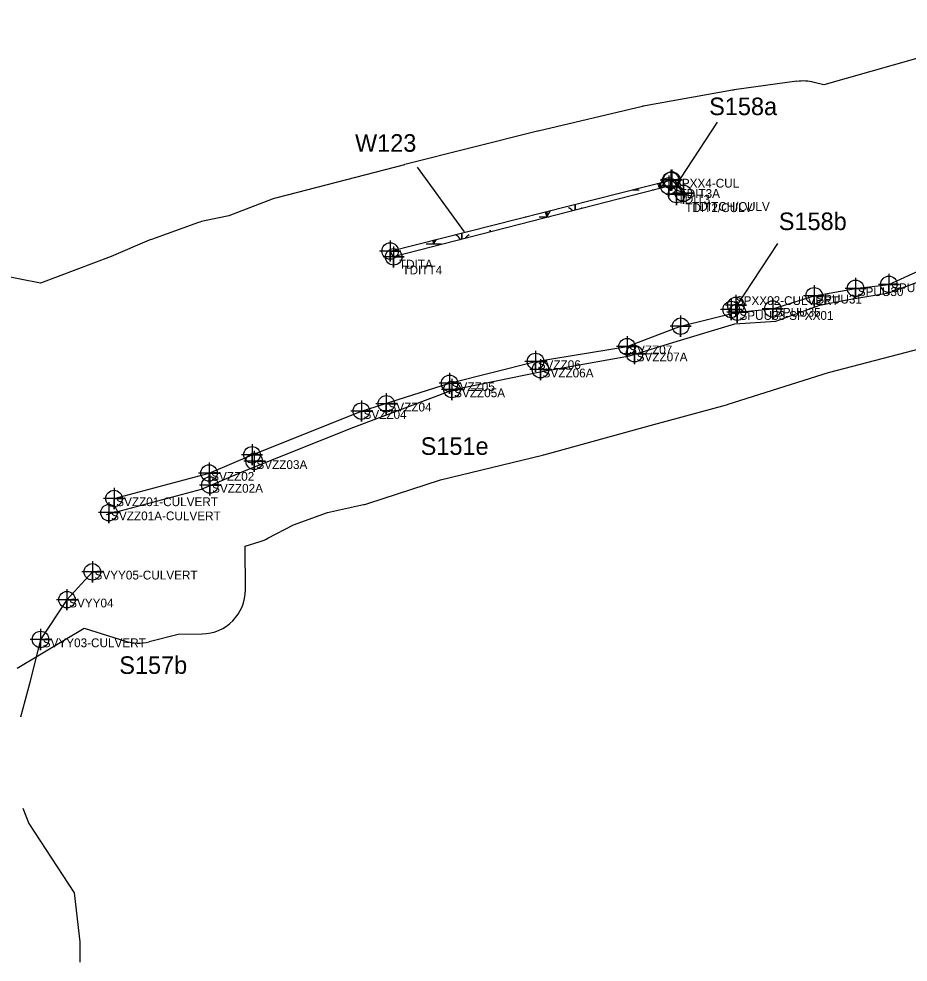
# Model space of a CAD drawing. Extents: x 1253697 to 1278588, y 912189 to 981699.
# Drawn here: x 1273061 to 1274074, y 979888 to 980962 of the extents above; entities that cross this region are included whole.
import ezdxf

# ---------------------------------------------------------------- set-up
doc = ezdxf.new("R2010")
doc.units = 0
for name, color, linetype in [('Default', 7, 'Continuous'), ('Exist Environmental Wetland Boundary', 7, 'Continuous'), ('Exist Environmental Wetland Boundary Cogo Comment', 7, 'Continuous'), ('Exist Environmental Wetland Boundary Cogo Number', 7, 'Continuous'), ('Exist Environmental Wetland Boundary Cogo Point CELL', 7, 'Continuous'), ('Exist Hydro Jurisdictional Stream or Body of Water Mitigable', 7, 'Continuous'), ('Exist Hydro Jurisdictional Stream or Body of Water Mitigable Cogo Comment', 7, 'Continuous'), ('Exist Hydro Jurisdictional Stream or Body of Water Mitigable Cogo Number', 7, 'Continuous'), ('Exist Hydro Jurisdictional Stream or Body of Water Mitigable Cogo Point CELL', 7, 'Continuous'), ('Exist Hydro Swamp or Marsh', 7, 'Continuous')]:
    doc.layers.add(name, color=color, linetype=linetype)

msp = doc.modelspace()

# ---------------------------------------------------------------- linework, layer by layer
at = {"layer": 'Default'}
for p, q in [((1273947.3, 980891.2), (1273875.7, 980881.4)), ((1273947.3, 980891.2), (1273875.7, 980881.4)), ((1273873.7, 980881), (1273774.2, 980863.3)), ((1273873.7, 980881), (1273774.2, 980863.3)), ((1273771.5, 980862.7), (1273652.5, 980834.5)), ((1273771.5, 980862.7), (1273652.5, 980834.5)), ((1273807.7, 980769.9), (1273856.7, 980844.7)), ((1273651.8, 980834.4), (1273500.5, 980796.4)), ((1273651.8, 980834.4), (1273500.5, 980796.4)), ((1273500.1, 980796.3), (1273354.7, 980758.6)), ((1273500.1, 980796.3), (1273354.7, 980758.6)), ((1273568.6, 980719.7), (1273514.9, 980793.6)), ((1273265.6, 980730.5), (1273212.1, 980711.2)), ((1273265.6, 980730.5), (1273212.1, 980711.2)), ((1273878.2, 980634.4), (1273925.6, 980706.7))]:
    msp.add_line(p, q, dxfattribs=at)
for points in [[(1274242.8, 980962.3), (1273978, 980887.1), (1273966.8, 980890)], [(1274242.8, 980962.3), (1273978, 980887.1), (1273966.8, 980890)], [(1273349.4, 980756.9), (1273300.1, 980738), (1273272.5, 980732.4)], [(1273349.4, 980756.9), (1273300.1, 980738), (1273272.5, 980732.4)], [(1273209.4, 980710.2), (1273166, 980691.7), (1273085.5, 980661.3), (1272899.9, 980697.9)], [(1273209.4, 980710.2), (1273166, 980691.7), (1273085.5, 980661.3), (1272899.9, 980697.9)], [(1273869, 980523.5), (1273983.3, 980559.8), (1274541, 980705)], [(1273869, 980523.5), (1273983.3, 980559.8), (1274541, 980705)], [(1273659.1, 980466), (1273784.3, 980500.3), (1273867.1, 980522.9)], [(1273659.1, 980466), (1273784.3, 980500.3), (1273867.1, 980522.9)], [(1273458.5, 980410.6), (1273541.2, 980437.5), (1273657.6, 980465.6)], [(1273458.5, 980410.6), (1273541.2, 980437.5), (1273657.6, 980465.6)], [(1273344.6, 980370.9), (1273373.8, 980386.3), (1273412.5, 980400.3), (1273453.7, 980409.3)], [(1273344.6, 980370.9), (1273373.8, 980386.3), (1273412.5, 980400.3), (1273453.7, 980409.3)], [(1273319, 980312.4), (1273318.6, 980362), (1273335.9, 980367.3)], [(1273319, 980312.4), (1273318.6, 980362), (1273335.9, 980367.3)], [(1273059, 980223.1), (1273135.4, 980268.4), (1273182.3, 980253.9)], [(1273059, 980223.1), (1273135.4, 980268.4), (1273182.3, 980253.9)], [(1273209.5, 980253.2), (1273242.4, 980261.7), (1273269.7, 980262)], [(1273209.5, 980253.2), (1273242.4, 980261.7), (1273269.7, 980262)]]:
    msp.add_lwpolyline(points, dxfattribs=at)
for centre, start, end in [((1273954.1, 980841.6), 75.3429, 97.8004), ((1273954.1, 980841.6), 75.3429, 97.8004), ((1273882.5, 980831.8), 97.8004, 100.1149), ((1273882.5, 980831.8), 97.8004, 100.1149), ((1273783, 980814.1), 100.1149, 103.3262), ((1273783, 980814.1), 100.1149, 103.3262), ((1273664, 980785.9), 103.3262, 104.0919), ((1273664, 980785.9), 103.3262, 104.0919), ((1273512.6, 980747.9), 104.0919, 104.5334), ((1273512.6, 980747.9), 104.0919, 104.5334), ((1273367.2, 980710.2), 104.5334, 110.925), ((1273367.2, 980710.2), 104.5334, 110.925), ((1273282.5, 980683.4), 101.5049, 109.7893), ((1273282.5, 980683.4), 101.5049, 109.7893), ((1273229, 980664.2), 109.7893, 113.0429), ((1273229, 980664.2), 109.7893, 113.0429), ((1273853.9, 980571.1), 285.2917, 287.6221), ((1273853.9, 980571.1), 285.2917, 287.6221), ((1273645.9, 980514.2), 283.5797, 285.3202), ((1273645.9, 980514.2), 283.5797, 285.3202), ((1273443, 980458.1), 282.3143, 288.0022), ((1273443, 980458.1), 282.3143, 288.0022), ((1273321.3, 980415.1), 287.0114, 297.8826), ((1273321.3, 980415.1), 287.0114, 297.8826), ((1273269, 980312), 270.8306, 0.3852), ((1273269, 980312), 270.8306, 0.3852), ((1273197.1, 980301.6), 252.8278, 284.412), ((1273197.1, 980301.6), 252.8278, 284.412)]:
    msp.add_arc(centre, 50, start, end, dxfattribs=at)
at = {"layer": 'Exist Environmental Wetland Boundary'}
msp.add_lwpolyline([(1273817.9, 980763.7), (1273801.3, 980772), (1273487.9, 980691.3), (1273483.9, 980698), (1273804.7, 980778.9)], close=True, dxfattribs=at)
at = {"layer": 'Exist Environmental Wetland Boundary Cogo Point CELL'}
for points in [[(1273803.5, 980790.5), (1273803.5, 980766.5), (1273803.5, 980778.5), (1273815.5, 980778.5), (1273791.5, 980778.5)], [(1273801.3, 980784), (1273801.3, 980760), (1273801.3, 980772), (1273813.3, 980772), (1273789.3, 980772)], [(1273817.9, 980775.7), (1273817.9, 980751.7), (1273817.9, 980763.7), (1273829.9, 980763.7), (1273805.9, 980763.7)], [(1273810.1, 980774.3), (1273810.1, 980750.3), (1273810.1, 980762.3), (1273822.1, 980762.3), (1273798.1, 980762.3)], [(1273483.9, 980710), (1273483.9, 980686), (1273483.9, 980698), (1273495.9, 980698), (1273471.9, 980698)], [(1273487.9, 980703.3), (1273487.9, 980679.3), (1273487.9, 980691.3), (1273499.9, 980691.3), (1273475.9, 980691.3)]]:
    msp.add_lwpolyline(points, dxfattribs=at)
for centre in [(1273803.5, 980778.5), (1273801.3, 980772), (1273810.1, 980762.3), (1273817.9, 980763.7), (1273483.9, 980698), (1273487.9, 980691.3)]:
    msp.add_circle(centre, 9.38, dxfattribs=at)
at = {"layer": 'Exist Hydro Jurisdictional Stream or Body of Water Mitigable'}
msp.add_line((1273804.7, 980778.9), (1273817.9, 980763.7), dxfattribs=at)
for points in [[(1273169.4, 980416.2), (1273277.6, 980445.2), (1273326.6, 980466), (1273451.1, 980515.7), (1273551.6, 980547.4), (1273649.5, 980572.3), (1273753.7, 980589.1), (1273814.8, 980612.4), (1273879.3, 980628.4), (1273919.7, 980632), (1273966.8, 980647), (1274014, 980655.5), (1274052, 980660), (1274091.9, 980678)], [(1273160.9, 980397.8), (1273269.1, 980426.8), (1273318.2, 980447.6), (1273442.6, 980497.3), (1273556.6, 980540.3), (1273654.8, 980560.5), (1273756.5, 980578.6), (1273810.9, 980595.4), (1273876.5, 980615.1), (1273923.2, 980618), (1273973.3, 980636.4), (1274004, 980642.3), (1274051.9, 980650.5), (1274089.4, 980664.5)], [(1273879.3, 980629.4), (1273877.7, 980636.2)], [(1273144.7, 980332.7), (1273115.8, 980301), (1273085.7, 980255.7), (1273073.6, 980206.8), (1273063, 980167.3)], [(1273065.4, 980063.7), (1273072.5, 980046), (1273123.9, 979967.1), (1273130.5, 979911.3), (1273130.4, 979888.3)]]:
    msp.add_lwpolyline(points, dxfattribs=at)
at = {"layer": 'Exist Hydro Jurisdictional Stream or Body of Water Mitigable Cogo Point CELL'}
for points in [[(1273804.7, 980790.9), (1273804.7, 980766.9), (1273804.7, 980778.9), (1273816.7, 980778.9), (1273792.7, 980778.9)], [(1274052, 980672), (1274052, 980648), (1274052, 980660), (1274064, 980660), (1274040, 980660)], [(1273966.8, 980659), (1273966.8, 980635), (1273966.8, 980647), (1273978.8, 980647), (1273954.8, 980647)], [(1274014, 980667.5), (1274014, 980643.5), (1274014, 980655.5), (1274026, 980655.5), (1274002, 980655.5)], [(1273877.7, 980648.2), (1273877.7, 980624.2), (1273877.7, 980636.2), (1273889.7, 980636.2), (1273865.7, 980636.2)], [(1273872.3, 980643.4), (1273872.3, 980619.4), (1273872.3, 980631.4), (1273884.3, 980631.4), (1273860.3, 980631.4)], [(1273879.3, 980640.4), (1273879.3, 980616.4), (1273879.3, 980628.4), (1273891.3, 980628.4), (1273867.3, 980628.4)], [(1273919.7, 980644), (1273919.7, 980620), (1273919.7, 980632), (1273931.7, 980632), (1273907.7, 980632)], [(1273814.8, 980624.4), (1273814.8, 980600.4), (1273814.8, 980612.4), (1273826.8, 980612.4), (1273802.8, 980612.4)], [(1273753.7, 980601.1), (1273753.7, 980577.1), (1273753.7, 980589.1), (1273765.7, 980589.1), (1273741.7, 980589.1)], [(1273762.2, 980593.1), (1273762.2, 980569.1), (1273762.2, 980581.1), (1273774.2, 980581.1), (1273750.2, 980581.1)], [(1273649.5, 980584.3), (1273649.5, 980560.3), (1273649.5, 980572.3), (1273661.5, 980572.3), (1273637.5, 980572.3)], [(1273655.1, 980574.9), (1273655.1, 980550.9), (1273655.1, 980562.9), (1273667.1, 980562.9), (1273643.1, 980562.9)], [(1273551.6, 980559.4), (1273551.6, 980535.4), (1273551.6, 980547.4), (1273563.6, 980547.4), (1273539.6, 980547.4)], [(1273554.3, 980552.3), (1273554.3, 980528.3), (1273554.3, 980540.3), (1273566.3, 980540.3), (1273542.3, 980540.3)], [(1273479.5, 980536), (1273479.5, 980512), (1273479.5, 980524), (1273491.5, 980524), (1273467.5, 980524)], [(1273451.1, 980527.7), (1273451.1, 980503.7), (1273451.1, 980515.7), (1273463.1, 980515.7), (1273439.1, 980515.7)], [(1273326.6, 980478), (1273326.6, 980454), (1273326.6, 980466), (1273338.6, 980466), (1273314.6, 980466)], [(1273329.1, 980470.6), (1273329.1, 980446.6), (1273329.1, 980458.6), (1273341.1, 980458.6), (1273317.1, 980458.6)], [(1273277.6, 980457.2), (1273277.6, 980433.2), (1273277.6, 980445.2), (1273289.6, 980445.2), (1273265.6, 980445.2)], [(1273278.6, 980443.5), (1273278.6, 980419.5), (1273278.6, 980431.5), (1273290.6, 980431.5), (1273266.6, 980431.5)], [(1273169.4, 980428.2), (1273169.4, 980404.2), (1273169.4, 980416.2), (1273181.4, 980416.2), (1273157.4, 980416.2)], [(1273163.6, 980412.1), (1273163.6, 980388.1), (1273163.6, 980400.1), (1273175.6, 980400.1), (1273151.6, 980400.1)], [(1273144.7, 980344.7), (1273144.7, 980320.7), (1273144.7, 980332.7), (1273156.7, 980332.7), (1273132.7, 980332.7)], [(1273115.8, 980313), (1273115.8, 980289), (1273115.8, 980301), (1273127.8, 980301), (1273103.8, 980301)], [(1273085.7, 980267.7), (1273085.7, 980243.7), (1273085.7, 980255.7), (1273097.7, 980255.7), (1273073.7, 980255.7)]]:
    msp.add_lwpolyline(points, dxfattribs=at)
for centre in [(1273804.7, 980778.9), (1274052, 980660), (1274014, 980655.5), (1273966.8, 980647), (1273872.3, 980631.4), (1273877.7, 980636.2), (1273879.3, 980628.4), (1273919.7, 980632), (1273814.8, 980612.4), (1273753.7, 980589.1), (1273762.2, 980581.1), (1273649.5, 980572.3), (1273655.1, 980562.9), (1273551.6, 980547.4), (1273554.3, 980540.3), (1273479.5, 980524), (1273451.1, 980515.7), (1273326.6, 980466), (1273329.1, 980458.6), (1273277.6, 980445.2), (1273278.6, 980431.5), (1273169.4, 980416.2), (1273163.6, 980400.1), (1273144.7, 980332.7), (1273115.8, 980301), (1273085.7, 980255.7)]:
    msp.add_circle(centre, 9.38, dxfattribs=at)
at = {"layer": 'Exist Hydro Swamp or Marsh'}
for p, q in [((1273791.1, 980769.4), (1273791.1, 980775.5)), ((1273791.1, 980775.5), (1273791.1, 980769.4)), ((1273759.7, 980767.6), (1273767.5, 980767.6)), ((1273782.5, 980767.6), (1273784.2, 980767.6)), ((1273694.5, 980744.5), (1273694.5, 980751.1)), ((1273694.5, 980751.1), (1273694.5, 980744.5)), ((1273637.6, 980736.8), (1273638.7, 980736.8)), ((1273565.7, 980711.3), (1273565.7, 980718.6)), ((1273565.7, 980718.6), (1273565.7, 980711.3))]:
    msp.add_line(p, q, dxfattribs=at)
for points in [[(1273653.7, 980736.8), (1273662.3, 980736.8), (1273662.3, 980743)], [(1273662.3, 980743), (1273662.3, 980736.8), (1273664.7, 980736.8)], [(1273597.9, 980719.6), (1273597.9, 980721.8), (1273597.9, 980719.6)], [(1273524.9, 980706), (1273533.5, 980706), (1273533.5, 980710.5)], [(1273533.5, 980710.5), (1273533.5, 980706), (1273542.1, 980706)]]:
    msp.add_lwpolyline(points, dxfattribs=at)
for centre, radius, start, end in [((1273809.4, 980761.5), 19.2, 124.4188, 155.2341), ((1273778.9, 980766.7), 12.3, 12.2673, 41.0136), ((1273680.6, 980730.7), 19.2, 135.7444, 161.6222), ((1273682.3, 980735.9), 12.3, 39.6791, 67.535), ((1273712.8, 980730.7), 19.2, 122.1274, 126.1298), ((1273650.1, 980735.9), 12.3, 4.1403, 32.6328), ((1273551.8, 980700), 19.2, 144.1997, 161.6222), ((1273553.4, 980705.1), 12.3, 28.184, 67.535), ((1273584, 980700), 19.2, 122.1274, 140.5018), ((1273521.2, 980705.1), 12.3, 4.1403, 24.6462)]:
    msp.add_arc(centre, radius, start, end, dxfattribs=at)

# ---------------------------------------------------------------- texts
at = {"layer": 'Exist Environmental Wetland Boundary Cogo Comment'}
for s, p in [('TDIT3A', (1273813.5, 980758.5)), ('TDIT3', (1273811.3, 980752)), ('TDITCH/CULV', (1273827.9, 980743.7)), ('TDIT2/CULV', (1273820.1, 980742.3)), ('TDITA', (1273493.9, 980678)), ('TDITT4', (1273497.9, 980671.3))]:
    msp.add_text(s, height=10, dxfattribs=at).set_placement(p)
at = {"layer": 'Exist Environmental Wetland Boundary Cogo Number'}
msp.add_text('W123', height=20, dxfattribs=at).set_placement((1273443.9, 980811))
at = {"layer": 'Exist Hydro Jurisdictional Stream or Body of Water Mitigable Cogo Comment'}
for s, p in [('SPXX4-CUL', (1273807.2, 980770.2)), ('SPUU29', (1274054.5, 980651.2)), ('SPXX02-CULVERT', (1273877.6, 980636.5)), ('SPUU31', (1273969.3, 980638.2)), ('SPUU30', (1274016.5, 980646.7)), ('SPUU33-SPXX01', (1273881.8, 980619.6)), ('SPUU35', (1273922.2, 980623.2)), ('SVZZ07', (1273756.2, 980580.4)), ('SVZZ07A', (1273764.7, 980572.4)), ('SVZZ06', (1273652, 980563.6)), ('SVZZ06A', (1273657.6, 980554.1)), ('SVZZ05', (1273554.1, 980538.6)), ('SVZZ05A', (1273556.8, 980531.5)), ('SVZZ04', (1273482, 980515.3)), ('SVZZ04', (1273453.6, 980506.9)), ('SVZZ03A', (1273331.6, 980449.8)), ('SVZZ02', (1273280.1, 980436.4)), ('SVZZ02A', (1273281.1, 980422.8)), ('SVZZ01-CULVERT', (1273171.9, 980407.5)), ('SVZZ01A-CULVERT', (1273166.1, 980391.4)), ('SVYY05-CULVERT', (1273147.2, 980324)), ('SVYY04', (1273118.3, 980292.2)), ('SVYY03-CULVERT', (1273088.2, 980246.9))]:
    msp.add_text(s, height=10, dxfattribs=at).set_placement(p)
at = {"layer": 'Exist Hydro Jurisdictional Stream or Body of Water Mitigable Cogo Number'}
for s, p in [('S158a', (1273847.3, 980852.7)), ('S158b', (1273926.6, 980721.8)), ('S151e', (1273518.7, 980465.9)), ('S157b', (1273175.4, 980216.5))]:
    msp.add_text(s, height=20, dxfattribs=at).set_placement(p)

doc.saveas('drawing.dxf')
